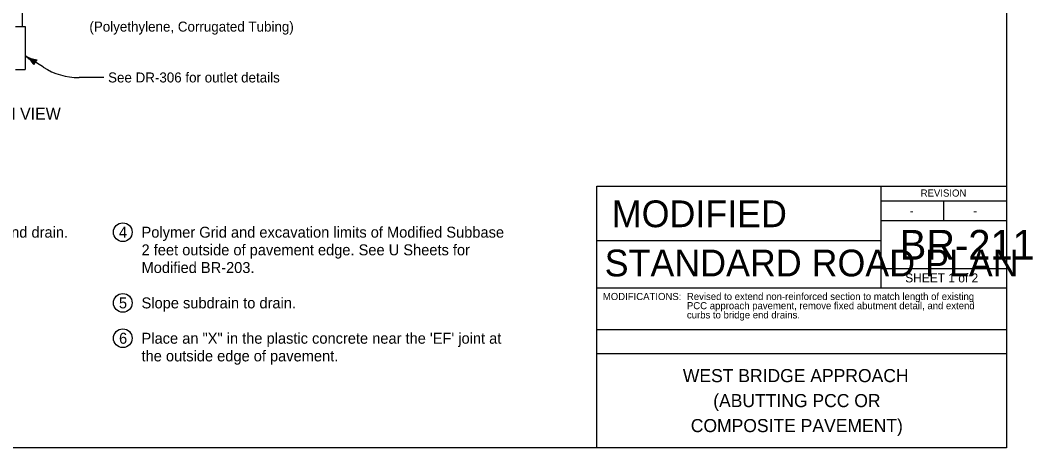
# Model space of a CAD drawing. Extents: x 9234 to 81668, y 5635 to 15999.
# Drawn here: x 22411 to 24112, y 7924 to 8643 of the extents above; entities that cross this region are included whole.
import ezdxf

# ---------------------------------------------------------------- set-up
doc = ezdxf.new("R2010")
doc.units = 0
for name, color, linetype in [('Alignment', 7, 'Continuous'), ('Level 61', 7, 'Continuous'), ('PS_BOLT', 7, 'Continuous'), ('PS_CONST', 7, 'Continuous'), ('PS_DIM', 7, 'Continuous'), ('SurEdgeShoulderUnpaved', 7, 'Continuous')]:
    doc.layers.add(name, color=color, linetype=linetype)

msp = doc.modelspace()

# ---------------------------------------------------------------- linework, layer by layer
at = {"layer": 'Level 61'}
msp.add_lwpolyline([(20932.5, 9944), (24067.5, 9944), (24067.5, 7924), (20932.5, 7924)], close=True, dxfattribs=at)
at = {"layer": 'PS_BOLT'}
for p, q in [((22449.4, 8563.7), (22418.8, 8582.9)), ((22551, 8546.5), (22509.4, 8546.5))]:
    msp.add_line(p, q, dxfattribs=at)
msp.add_arc((22509.4, 8659.5), 113.1, 237.9168, 270, dxfattribs=at)
at = {"layer": 'PS_DIM'}
for p, q in [((22413.7, 8747.8), (22413.7, 8632.1)), ((22402.4, 8632.1), (22418.8, 8632.1)), ((22418.8, 8632.1), (22418.8, 8559.7)), ((22418.8, 8582.9), (22435.6, 8572.4)), ((22402.4, 8559.7), (22418.8, 8559.7))]:
    msp.add_line(p, q, dxfattribs=at)
msp.add_lwpolyline([(22437.2, 8575.7), (22434.6, 8573), (22433.3, 8569.4), (22430.6, 8573.6), (22425.5, 8578.6), (22432.9, 8576.1), (22436.4, 8575.6), (22434, 8573.3), (22433, 8571.2), (22431.3, 8573.9), (22428.5, 8576.8), (22432.6, 8575.6), (22434.9, 8575.1), (22432.9, 8572.6), (22431.1, 8575.2), (22433.4, 8574.6), (22432.8, 8573.7), (22432.1, 8574.5)], dxfattribs=at)
for centre in [(22582.9, 8286.4), (22582.9, 8167.5), (22582.9, 8108.1)]:
    msp.add_circle(centre, 15.7, dxfattribs=at)
for centre, radius, start, end in [((22395.6, 8545.9), 43.7, 29.8434, 57.9159), ((22442, 8619.9), 43.7, 237.9159, 265.9884), ((22449.9, 8563.4), 16.9, 130.1825, 165.6492)]:
    msp.add_arc(centre, radius, start, end, dxfattribs=at)
at = {"layer": 'SurEdgeShoulderUnpaved'}
for p, q in [((23856.6, 8364), (23856.6, 8272.7)), ((23856.6, 8339.1), (24067.5, 8339.1)), ((23962.1, 8339.1), (23962.1, 8305.9)), ((23856.6, 8305.9), (24067.5, 8305.9)), ((23379.5, 8272.7), (23856.6, 8272.7)), ((23856.6, 8272.7), (23856.6, 8192.7)), ((24067.5, 8224.9), (23856.6, 8224.9)), ((23379.5, 8192.7), (24067.5, 8192.7)), ((23379.5, 8122.7), (24067.5, 8122.7)), ((23379.5, 8082.7), (24067.5, 8082.7)), ((23379.5, 8082.7), (24067.5, 8082.7))]:
    msp.add_line(p, q, dxfattribs=at)
msp.add_lwpolyline([(23379.5, 8364), (24067.5, 8364), (24067.5, 7924), (23379.5, 7924)], close=True, dxfattribs=at)

# ---------------------------------------------------------------- texts
at = {"layer": 'Alignment'}
for s, height, p in [('MODIFIED', 45, (23404.6, 8294.8)), ('MODIFICATIONS:', 12, (23389.5, 8172.3))]:
    msp.add_text(s, height=height, dxfattribs=at).set_placement(p)
at = {"layer": 'PS_BOLT'}
for s, height, p in [('(Polyethylene, Corrugated Tubing)', 16.8, (22526.8, 8623.6)), ('See DR-306 for outlet details', 16.8, (22558.2, 8538.1)), ('Continue 4 inch Sloped Curb to edge of the bridge end drain.', 18.375, (21828.4, 8277.2)), ('4', 18.4, (22576.4, 8277.2)), ('Polymer Grid and excavation limits of Modified Subbase', 18.375, (22614.4, 8277.2)), ('2 feet outside of pavement edge. See U Sheets for', 18.375, (22614.4, 8247.5)), ('Modified BR-203.', 18.375, (22614.4, 8217.8)), ('5', 18.4, (22576.4, 8158.3)), ('Slope subdrain to drain.', 18.375, (22614.4, 8158.3)), ('6', 18.4, (22576.6, 8098.9)), ('Place an "X" in the plastic concrete near the \'EF\' joint at', 18.375, (22614.4, 8098.9)), ('the outside edge of pavement.', 18.375, (22614.4, 8069.2))]:
    msp.add_text(s, height=height, dxfattribs=at).set_placement(p)
at = {"layer": 'PS_CONST'}
msp.add_text('PLAN VIEW', height=20, dxfattribs=at).set_placement((22333, 8475.6))
at = {"layer": 'SurEdgeShoulderUnpaved'}
for s, height, p in [('REVISION', 12, (23923.6, 8346.2)), ('-', 15, (23905.1, 8314.7)), ('-', 15, (24011.6, 8315.1)), ('BR-211', 50, (23888.4, 8240.2)), ('STANDARD ROAD PLAN', 45.001, (23392.6, 8212.1)), ('SHEET 1 of 2', 15, (23897.6, 8202)), ('Revised to extend non-reinforced section to match length of existing ', 12, (23530.8, 8172.4)), ('PCC approach pavement, remove fixed abutment detail, and extend ', 12, (23530.8, 8156.9)), ('curbs to bridge end drains.', 12, (23530.8, 8141.4)), ('WEST BRIDGE APPROACH', 22, (23524, 8034.3)), ('(ABUTTING PCC OR', 22, (23575, 7992.3)), ('COMPOSITE PAVEMENT)', 22, (23537.3, 7950.3))]:
    msp.add_text(s, height=height, dxfattribs=at).set_placement(p)

doc.saveas('drawing.dxf')
